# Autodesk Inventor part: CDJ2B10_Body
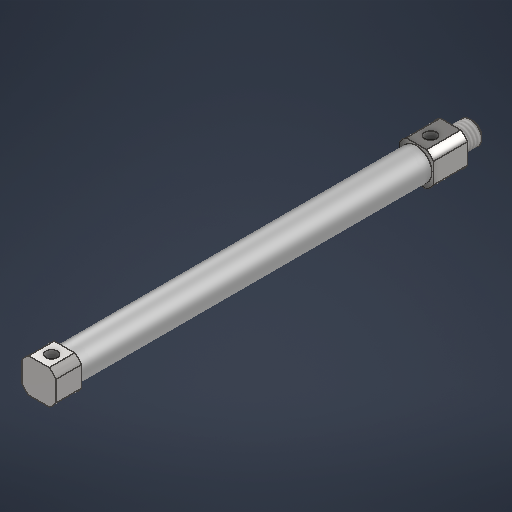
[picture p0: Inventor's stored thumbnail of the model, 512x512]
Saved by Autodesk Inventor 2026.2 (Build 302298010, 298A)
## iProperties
Created: 2026-05
Part Number: CDJ2B10_Body
Material: 스테인리스스틸
Document SubType Name: Modeling
Designer: work
Density: 8 g/cm^3
Appearance: 반연마
Author: work
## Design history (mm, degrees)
sketch "스케치1"
  geometry: C1 r 5.5 at (0, 0); 1 further point
  constraints: 1 centre point, 1 coincident
  dimensions: "d0" = 11 diameter of C1
extrude "돌출1" new body sketch "스케치1" distance "d1" = 124; taper "d2" = 0 deg
sketch "스케치2"
  geometry: L1 (-6, -6)-(6, -6); L2 (6, -6)-(6, 6); L3 (6, 6)-(-6, 6); L4 (-6, 6)-(-6, -6); L5 (-6, -6)-(6, 6); L6 (6, -6)-(-6, 6); C1 r 7 at (0, 0); 9 further points
  constraints: 12 end point, 2 midpoint, 2 parallel, 1 centre point, 1 coincident, 1 horizontal, 1 perpendicular
  dimensions: "d3" = 14 diameter of C1; "d4" = 12 distance between parallel lines of L1 L3; "d5" = 12 distance of L1.start L1.end
extrude "돌출2" join sketch "스케치2" distance "d6" = 9; taper "d7" = 0 deg
sketch "스케치3"
  geometry: L1 (-6, 6)-(6, 6); L2 (6, 6)-(6, -6); L3 (6, -6)-(-6, -6); L4 (-6, -6)-(-6, 6); L5 (-6, 6)-(6, -6); L6 (6, 6)-(-6, -6); L7 (6, 3.606)-(6, -3.606) reference; 9 further points
  constraints: 12 end point, 2 midpoint, 2 parallel, 1 coincident, 1 horizontal, 1 perpendicular, 3 other
  dimensions: "d8" = 12 distance of L2.end L3.end; "d9" = 12 distance of L1.end L2.end
extrude "돌출3" join sketch "스케치3" distance "d10" = 12; taper "d11" = 0 deg
sketch "스케치4"
  geometry: C1 r 4 at (0, 0); 1 further point
  constraints: 1 centre point, 1 coincident
  dimensions: "d12" = 8 diameter of C1
extrude "돌출4" join sketch "스케치4" distance "d13" = 8; taper "d14" = 0 deg
feature "스레드1" dims "d15" = 8, "d16" = 0
chamfer "모따기1" distance "d17" = 1; stored, may be unused: second distance "d18" = 2, angle "d19" = 45 deg
sketch "스케치5"
  geometry: L1 (0, 124)-(7.211, 124) reference; L2 (7.211, 124)-(7.211, 136) reference; L3 (0, 136)-(7.211, 136) reference; L4 (0, 124)-(0, 136) reference; L5 (7.211, 0)-(0, 0) reference; L6 (0, 0)-(0, -9) reference; L7 (7.211, -9)-(0, -9) reference; L8 (7.211, 0)-(7.211, -9) reference; L9 (0, -4.5)-(7.211, -4.5); L10 (3.606, 124)-(3.606, 136); 2 further points
  constraints: 4 end point, 4 midpoint, 1 point on line
  dimensions: "d20" = 5 distance from line of L1 point (3.606, 129)
hole "구멍1" sketch "스케치5" at (3.606, -4.5), (3.606, 129) diameter "d21" = 4.134; stored, may be unused: countersink angle "d25" = 90 deg, drill point angle "d27" = 0 deg; dims "d22" = 5, "d23" = 5, "d24" = 1, "d26" = 5
sketch "스케치6"
  geometry: C1 r 2 at (0, 0); 1 further point
  constraints: 1 centre point, 1 coincident
  dimensions: "d28" = 4 diameter of C1
extrude "돌출5" cut sketch "스케치6" distance "d29" = 142; taper "d30" = 0 deg
node "솔리드1"
node "투영된 루프1"
node "투영된 루프2"
feature "A9D066F2-1C7D-4E18-AEED-F7BC21143FA4" dims "d15" = 8, "d16" = 0
